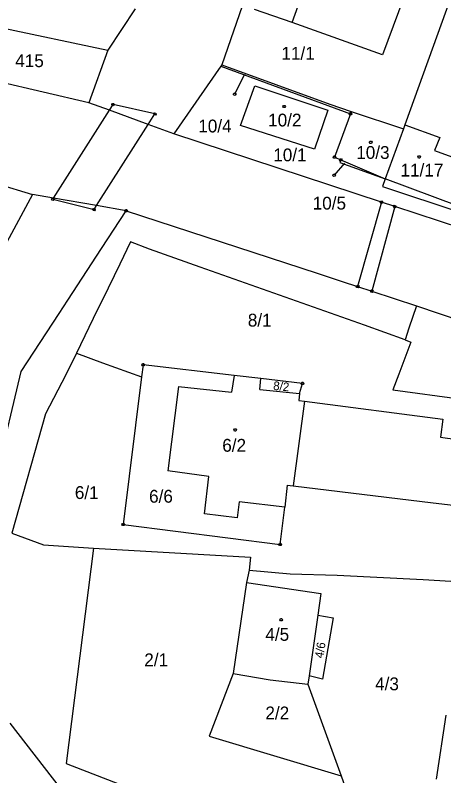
# Model space of a CAD drawing. Extents: x -634640 to -629202, y -1196156 to -1190068.
# Drawn here: x -631593.2 to -631536.4, y -1192622.8 to -1192521.9 of the extents above; entities that cross this region are included whole.
import ezdxf

# ---------------------------------------------------------------- set-up
doc = ezdxf.new("R2010")
doc.units = 0
for name, color, linetype in [('Vrstva 1', 7, 'Continuous'), ('Vrstva 2', 7, 'Continuous'), ('Vrstva 3', 7, 'Continuous'), ('Vrstva 4', 7, 'Continuous'), ('Vrstva 5', 7, 'Continuous'), ('Vrstva 7', 7, 'Continuous'), ('Vrstva 8', 7, 'Continuous')]:
    doc.layers.add(name, color=color, linetype=linetype)

msp = doc.modelspace()

# ---------------------------------------------------------------- linework, layer by layer
at = {"layer": 'Vrstva 1'}
for p, q in [((-631559.96, -1192511.39), (-631565.82, -1192528.47)), ((-631556.51, -1192522.86), (-631553.93, -1192515.63)), ((-631534.56, -1192517.11), (-631541.55, -1192536.43)), ((-631541.51, -1192519), (-631544.51, -1192527.15)), ((-631577.34, -1192521.05), (-631580.95, -1192526.53)), ((-631556.51, -1192522.86), (-631561.49, -1192521.13)), ((-631601.99, -1192522.05), (-631580.95, -1192526.53)), ((-631544.51, -1192527.15), (-631556.51, -1192522.86)), ((-631580.95, -1192526.53), (-631583.46, -1192533.5)), ((-631583.46, -1192533.5), (-631603.35, -1192528.86)), ((-631565.95, -1192528.66), (-631572.19, -1192537.61)), ((-631565.82, -1192528.47), (-631565.95, -1192528.66)), ((-631565.95, -1192528.66), (-631548.77, -1192534.95)), ((-631565.82, -1192528.47), (-631551.5, -1192533.69)), ((-631563.34, -1192536.5), (-631561.43, -1192531.25)), ((-631561.43, -1192531.25), (-631551.77, -1192534.48)), ((-631580.75, -1192534.49), (-631583.46, -1192533.5)), ((-631551.5, -1192533.69), (-631548.66, -1192534.64)), ((-631575.59, -1192536.37), (-631580.75, -1192534.49)), ((-631551.77, -1192534.48), (-631553.52, -1192539.67)), ((-631548.77, -1192534.95), (-631550.9, -1192540.69)), ((-631548.66, -1192534.64), (-631548.77, -1192534.95)), ((-631548.66, -1192534.64), (-631541.74, -1192536.95)), ((-631624.87, -1192535.23), (-631590.93, -1192545.67)), ((-631572.19, -1192537.61), (-631575.59, -1192536.37)), ((-631553.52, -1192539.67), (-631563.34, -1192536.5)), ((-631541.74, -1192536.95), (-631544.15, -1192543.59)), ((-631541.55, -1192536.43), (-631541.74, -1192536.95)), ((-631544.63, -1192546.68), (-631572.19, -1192537.61)), ((-631550.9, -1192540.69), (-631550.04, -1192541.06)), ((-631550.04, -1192541.06), (-631544.15, -1192543.59)), ((-631544.15, -1192543.59), (-631544.52, -1192544.62)), ((-631544.52, -1192544.62), (-631533.13, -1192548.37)), ((-631590.93, -1192545.67), (-631610.44, -1192581.5)), ((-631588.16, -1192546.15), (-631590.93, -1192545.67)), ((-631582.45, -1192547.13), (-631588.16, -1192546.15)), ((-631578.53, -1192547.81), (-631582.45, -1192547.13)), ((-631542.89, -1192547.25), (-631544.63, -1192546.68)), ((-631506.73, -1192559.15), (-631542.89, -1192547.25)), ((-631581.8, -1192552.82), (-631578.53, -1192547.81)), ((-631578.53, -1192547.81), (-631553.19, -1192556.1)), ((-631577.95, -1192551.95), (-631579.37, -1192554.89)), ((-631575.44, -1192552.92), (-631577.95, -1192551.95)), ((-631586.27, -1192559.67), (-631581.8, -1192552.82)), ((-631568.71, -1192555.28), (-631575.44, -1192552.92)), ((-631579.37, -1192554.89), (-631581.67, -1192559.63)), ((-631546.91, -1192562.99), (-631568.71, -1192555.28)), ((-631553.19, -1192556.1), (-631549.86, -1192557.2)), ((-631549.86, -1192557.2), (-631547.81, -1192557.87)), ((-631547.81, -1192557.87), (-631545.93, -1192558.48)), ((-631545.93, -1192558.48), (-631540.01, -1192560.42)), ((-631587.43, -1192561.45), (-631586.27, -1192559.67)), ((-631581.67, -1192559.63), (-631582.35, -1192561.02)), ((-631582.35, -1192561.02), (-631585.1, -1192566.69)), ((-631540.01, -1192560.42), (-631541.01, -1192563.41)), ((-631540.01, -1192560.42), (-631516.62, -1192568.44)), ((-631592.45, -1192569.13), (-631587.43, -1192561.45)), ((-631541.52, -1192564.95), (-631546.91, -1192562.99)), ((-631541.01, -1192563.41), (-631541.52, -1192564.95)), ((-631540.74, -1192565.23), (-631542.36, -1192569.48)), ((-631541.52, -1192564.95), (-631540.74, -1192565.23)), ((-631585.1, -1192566.69), (-631586.52, -1192569.6)), ((-631585.1, -1192566.69), (-631581.66, -1192568)), ((-631581.66, -1192568), (-631576.47, -1192569.84)), ((-631576.27, -1192568.25), (-631576.47, -1192569.84)), ((-631564.18, -1192569.66), (-631576.27, -1192568.25)), ((-631597.26, -1192589.32), (-631592.45, -1192569.13)), ((-631586.52, -1192569.6), (-631589.24, -1192574.75)), ((-631576.47, -1192569.84), (-631578.94, -1192589.43)), ((-631564.18, -1192569.66), (-631564.54, -1192571.88)), ((-631560.65, -1192570.07), (-631564.18, -1192569.66)), ((-631560.8, -1192571.53), (-631560.65, -1192570.07)), ((-631555.13, -1192570.71), (-631560.65, -1192570.07)), ((-631542.36, -1192569.48), (-631543.16, -1192571.58)), ((-631571.58, -1192571.11), (-631573.01, -1192582.33)), ((-631571.58, -1192571.11), (-631564.54, -1192571.88)), ((-631555.52, -1192572.06), (-631555.13, -1192570.71)), ((-631560.8, -1192571.53), (-631555.52, -1192572.06)), ((-631555.52, -1192572.06), (-631555.61, -1192573)), ((-631543.16, -1192571.58), (-631533.87, -1192572.85)), ((-631554.87, -1192573.09), (-631556.37, -1192584.31)), ((-631555.61, -1192573), (-631554.87, -1192573.09)), ((-631554.87, -1192573.09), (-631536.52, -1192575.47)), ((-631589.24, -1192574.75), (-631593.71, -1192590.59)), ((-631536.52, -1192575.47), (-631536.83, -1192577.85)), ((-631536.83, -1192577.85), (-631534.62, -1192578.17)), ((-631557.14, -1192584.22), (-631557.48, -1192587.12)), ((-631557.14, -1192584.22), (-631556.37, -1192584.31)), ((-631556.37, -1192584.31), (-631537.8, -1192586.57)), ((-631537.8, -1192586.57), (-631535.13, -1192586.89)), ((-631558.08, -1192592.08), (-631557.48, -1192587.12)), ((-631578.94, -1192589.43), (-631558.08, -1192592.08)), ((-631593.71, -1192590.59), (-631589.47, -1192592.13)), ((-631589.47, -1192592.13), (-631582.85, -1192592.59)), ((-631582.85, -1192592.59), (-631586.5, -1192621.15)), ((-631582.85, -1192592.59), (-631562.03, -1192593.76)), ((-631562.03, -1192593.76), (-631562.2, -1192595.47)), ((-631562.2, -1192595.47), (-631562.57, -1192597.13)), ((-631562.2, -1192595.47), (-631556.75, -1192595.99)), ((-631556.75, -1192595.99), (-631550.54, -1192596.15)), ((-631550.54, -1192596.15), (-631539.12, -1192596.73)), ((-631562.57, -1192597.13), (-631564.34, -1192609.18)), ((-631562.57, -1192597.13), (-631552.69, -1192598.6)), ((-631539.12, -1192596.73), (-631528.72, -1192597.36)), ((-631552.69, -1192598.6), (-631553.1, -1192601.48)), ((-631553.1, -1192601.48), (-631554.24, -1192609.49)), ((-631553.1, -1192601.48), (-631551.04, -1192601.81)), ((-631551.04, -1192601.81), (-631552.47, -1192609.96)), ((-631564.34, -1192609.18), (-631567.49, -1192617.5)), ((-631564.34, -1192609.18), (-631559.4, -1192610.03)), ((-631554.24, -1192609.49), (-631554.4, -1192610.63)), ((-631552.47, -1192609.96), (-631554.24, -1192609.49)), ((-631559.4, -1192610.03), (-631554.4, -1192610.63)), ((-631554.4, -1192610.63), (-631550.01, -1192622.76)), ((-631536.09, -1192614.71), (-631537.41, -1192623.23)), ((-631587.22, -1192624.4), (-631593.92, -1192615.79)), ((-631567.49, -1192617.5), (-631550.01, -1192622.76)), ((-631586.5, -1192621.15), (-631568.02, -1192628.22)), ((-631550.01, -1192622.76), (-631548.34, -1192627.37))]:
    msp.add_line(p, q, dxfattribs=at)
for points in [[(-631541.55, -1192536.43), (-631536.91, -1192538.1), (-631537.6, -1192539.82), (-631532.53, -1192541.67), (-631534.57, -1192547.16), (-631544.15, -1192543.59)], [(-631550.04, -1192541.06), (-631550.18, -1192541.4), (-631544.15, -1192543.59)], [(-631557.48, -1192587.12), (-631563.54, -1192586.41), (-631563.78, -1192588.57), (-631568.11, -1192588), (-631567.54, -1192583.08), (-631573.01, -1192582.33)]]:
    msp.add_lwpolyline(points, dxfattribs=at)
at = {"layer": 'Vrstva 3'}
msp.add_lwpolyline([(-631545.99, -1192538.59), (-631545.9, -1192538.74), (-631545.99, -1192538.89), (-631546.17, -1192538.89), (-631546.26, -1192538.74), (-631546.17, -1192538.59), (-631545.99, -1192538.59)], dxfattribs=at)
at = {"layer": 'Vrstva 4'}
for p, q in [((-631580.75, -1192534.49), (-631580.27, -1192533.73)), ((-631574.7, -1192534.98), (-631580.27, -1192533.73)), ((-631588.16, -1192546.15), (-631580.75, -1192534.49)), ((-631575.59, -1192536.37), (-631574.7, -1192534.98)), ((-631582.45, -1192547.13), (-631575.59, -1192536.37)), ((-631588.26, -1192546.3), (-631588.16, -1192546.15)), ((-631588.26, -1192546.3), (-631582.79, -1192547.66)), ((-631582.79, -1192547.66), (-631582.45, -1192547.13)), ((-631544.63, -1192546.68), (-631547.81, -1192557.87)), ((-631542.89, -1192547.25), (-631545.93, -1192558.48))]:
    msp.add_line(p, q, dxfattribs=at)
for points in [[(-631580.197, -1192533.889), (-631580.372, -1192533.878), (-631580.445, -1192533.719), (-631580.343, -1192533.571), (-631580.168, -1192533.582), (-631580.095, -1192533.741), (-631580.197, -1192533.889)], [(-631574.821, -1192535.106), (-631574.875, -1192534.94), (-631574.754, -1192534.814), (-631574.579, -1192534.854), (-631574.525, -1192535.02), (-631574.646, -1192535.146), (-631574.821, -1192535.106)], [(-631588.134, -1192546.178), (-631588.086, -1192546.347), (-631588.212, -1192546.468), (-631588.386, -1192546.422), (-631588.434, -1192546.253), (-631588.308, -1192546.132), (-631588.134, -1192546.178)], [(-631544.537, -1192546.828), (-631544.712, -1192546.84), (-631544.805, -1192546.692), (-631544.723, -1192546.532), (-631544.548, -1192546.52), (-631544.455, -1192546.668), (-631544.537, -1192546.828)], [(-631543.001, -1192547.385), (-631543.068, -1192547.223), (-631542.957, -1192547.088), (-631542.779, -1192547.115), (-631542.712, -1192547.277), (-631542.823, -1192547.412), (-631543.001, -1192547.385)], [(-631582.857, -1192547.499), (-631582.683, -1192547.515), (-631582.616, -1192547.676), (-631582.723, -1192547.821), (-631582.897, -1192547.805), (-631582.964, -1192547.644), (-631582.857, -1192547.499)], [(-631547.715, -1192557.723), (-631547.63, -1192557.876), (-631547.725, -1192558.023), (-631547.905, -1192558.017), (-631547.99, -1192557.864), (-631547.895, -1192557.717), (-631547.715, -1192557.723)], [(-631545.994, -1192558.317), (-631545.821, -1192558.337), (-631545.756, -1192558.5), (-631545.866, -1192558.643), (-631546.039, -1192558.623), (-631546.104, -1192558.46), (-631545.994, -1192558.317)]]:
    msp.add_lwpolyline(points, dxfattribs=at)
at = {"layer": 'Vrstva 5'}
for points in [[(-631557.47, -1192533.84), (-631557.38, -1192533.99), (-631557.47, -1192534.14), (-631557.65, -1192534.14), (-631557.74, -1192533.99), (-631557.65, -1192533.84), (-631557.47, -1192533.84)], [(-631539.57, -1192540.53), (-631539.48, -1192540.68), (-631539.57, -1192540.83), (-631539.75, -1192540.83), (-631539.84, -1192540.68), (-631539.75, -1192540.53), (-631539.57, -1192540.53)], [(-631563.98, -1192576.74), (-631563.89, -1192576.89), (-631563.98, -1192577.04), (-631564.16, -1192577.04), (-631564.25, -1192576.89), (-631564.16, -1192576.74), (-631563.98, -1192576.74)], [(-631557.88, -1192601.91), (-631557.79, -1192602.06), (-631557.88, -1192602.21), (-631558.06, -1192602.21), (-631558.15, -1192602.06), (-631558.06, -1192601.91), (-631557.88, -1192601.91)]]:
    msp.add_lwpolyline(points, dxfattribs=at)
at = {"layer": 'Vrstva 7'}
for p, q in [((-631562.81, -1192529.73), (-631564.13, -1192532.37)), ((-631549.55, -1192541.49), (-631550.93, -1192543.11))]:
    msp.add_line(p, q, dxfattribs=at)
for points in [[(-631564.277, -1192532.464), (-631564.291, -1192532.29), (-631564.144, -1192532.196), (-631563.983, -1192532.276), (-631563.969, -1192532.45), (-631564.116, -1192532.544), (-631564.277, -1192532.464)], [(-631551.096, -1192543.165), (-631551.067, -1192542.993), (-631550.901, -1192542.938), (-631550.764, -1192543.055), (-631550.793, -1192543.227), (-631550.959, -1192543.282), (-631551.096, -1192543.165)]]:
    msp.add_lwpolyline(points, dxfattribs=at)
at = {"layer": 'Vrstva 8'}
for points in [[(-631548.68, -1192534.8), (-631548.59, -1192534.95), (-631548.68, -1192535.1), (-631548.86, -1192535.1), (-631548.95, -1192534.95), (-631548.86, -1192534.8), (-631548.68, -1192534.8)], [(-631550.81, -1192540.54), (-631550.72, -1192540.69), (-631550.81, -1192540.84), (-631550.99, -1192540.84), (-631551.08, -1192540.69), (-631550.99, -1192540.54), (-631550.81, -1192540.54)], [(-631549.95, -1192540.91), (-631549.86, -1192541.06), (-631549.95, -1192541.21), (-631550.13, -1192541.21), (-631550.22, -1192541.06), (-631550.13, -1192540.91), (-631549.95, -1192540.91)], [(-631578.44, -1192547.66), (-631578.35, -1192547.81), (-631578.44, -1192547.96), (-631578.62, -1192547.96), (-631578.71, -1192547.81), (-631578.62, -1192547.66), (-631578.44, -1192547.66)], [(-631576.18, -1192568.1), (-631576.09, -1192568.25), (-631576.18, -1192568.4), (-631576.36, -1192568.4), (-631576.45, -1192568.25), (-631576.36, -1192568.1), (-631576.18, -1192568.1)], [(-631555.04, -1192570.56), (-631554.95, -1192570.71), (-631555.04, -1192570.86), (-631555.22, -1192570.86), (-631555.31, -1192570.71), (-631555.22, -1192570.56), (-631555.04, -1192570.56)], [(-631578.85, -1192589.28), (-631578.76, -1192589.43), (-631578.85, -1192589.58), (-631579.03, -1192589.58), (-631579.12, -1192589.43), (-631579.03, -1192589.28), (-631578.85, -1192589.28)], [(-631557.99, -1192591.93), (-631557.9, -1192592.08), (-631557.99, -1192592.23), (-631558.17, -1192592.23), (-631558.26, -1192592.08), (-631558.17, -1192591.93), (-631557.99, -1192591.93)]]:
    msp.add_lwpolyline(points, dxfattribs=at)

# ---------------------------------------------------------------- texts
at = {"layer": 'Vrstva 2'}
for s, height, p in [('11/1', 1.7, (-631557.927, -1192527.78)), ('415', 1.7, (-631593.243, -1192528.77)), ('10/4', 0.1, (-631562.97, -1192529.73)), ('10/2', 1.7, (-631559.687, -1192536.64)), ('10/3', 1.7, (-631547.997, -1192540.94)), ('10/1', 1.7, (-631559.007, -1192541.26)), ('10/5', 0.1, (-631549.708, -1192541.49)), ('11/17', 1.7, (-631542.121, -1192543.28)), ('8/1', 1.7, (-631562.383, -1192563.18)), ('6/2', 1.7, (-631565.773, -1192579.78)), ('6/1', 1.7, (-631585.333, -1192586.05)), ('6/6', 1.7, (-631575.483, -1192586.54)), ('4/5', 1.7, (-631560.053, -1192604.86)), ('2/1', 1.7, (-631576.123, -1192608.24)), ('4/3', 1.7, (-631545.493, -1192611.42)), ('2/2', 1.7, (-631560.053, -1192615.28))]:
    msp.add_text(s, height=height, dxfattribs=at).set_placement(p)
for s, rotation, p in [('8/2', 354.3171, (-631559.052, -1192571.566)), ('4/6', 81.01623, (-631552.391, -1192607.233))]:
    msp.add_text(s, height=1.14, rotation=rotation, dxfattribs=at).set_placement(p)
at = {"layer": 'Vrstva 7'}
for s, p in [('10/4', (-631568.954, -1192537.43)), ('10/5', (-631553.774, -1192547.66))]:
    msp.add_text(s, height=1.7, dxfattribs=at).set_placement(p)

doc.saveas('drawing.dxf')
